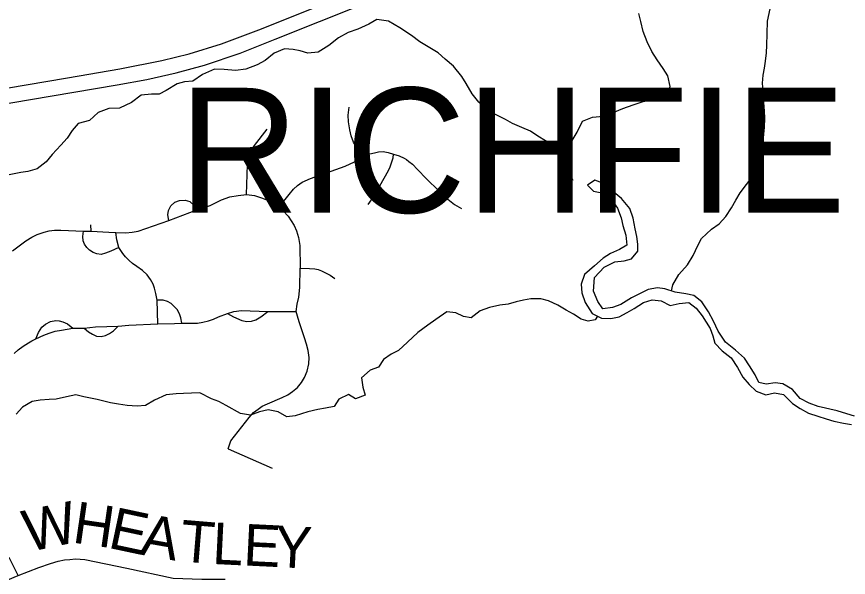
# Model space of a CAD drawing. Extents: x 0 to 34, y 0 to 22.
# Drawn here: x 6.774 to 7.911, y 17.175 to 17.94 of the extents above; entities that cross this region are included whole.
import ezdxf

# ---------------------------------------------------------------- set-up
doc = ezdxf.new("R2010")
doc.units = 0
for name, color, linetype in [('GM_X_County_Road', 7, 'Continuous'), ('GM_X_County_Road_Text', 7, 'Continuous'), ('GM_X_Interstate_Route', 7, 'Continuous'), ('GM_X_Minor_River', 7, 'Continuous'), ('GM_X_Township_Road', 7, 'Continuous'), ('GM_X_Township_Text', 7, 'Continuous')]:
    doc.layers.add(name, color=color, linetype=linetype)

msp = doc.modelspace()

# ---------------------------------------------------------------- linework, layer by layer
at = {"layer": 'GM_X_County_Road'}
msp.add_lwpolyline([(6.3969, 17.1561), (6.4792, 17.1605), (6.4835, 17.1608), (6.5551, 17.1657), (6.5991, 17.1683), (6.611, 17.1686), (6.6385, 17.1673), (6.6798, 17.1614), (6.7109, 17.1587), (6.7298, 17.1607), (6.7479, 17.1657), (6.7764, 17.1772), (6.8049, 17.1881), (6.8209, 17.1938), (6.8314, 17.197), (6.8397, 17.1986), (6.8472, 17.1994), (6.8548, 17.2001), (6.8677, 17.1991), (6.9249, 17.1872), (6.9884, 17.1736), (7.0275, 17.1723), (7.0591, 17.1724)], dxfattribs=at)
at = {"layer": 'GM_X_Interstate_Route'}
for points in [[(6.6481, 17.8024), (6.7935, 17.827), (6.9118, 17.8473), (6.9521, 17.8545), (6.9922, 17.8634), (7.0311, 17.8739), (7.0796, 17.8904), (7.1275, 17.9096), (7.3095, 17.9823)], [(6.7605, 17.8426), (6.8439, 17.8568), (6.9153, 17.869), (6.9726, 17.8806), (7.0103, 17.8893), (7.0541, 17.9032), (7.1051, 17.9225), (7.2044, 17.9618)]]:
    msp.add_lwpolyline(points, dxfattribs=at)
at = {"layer": 'GM_X_Minor_River'}
for points in [[(7.5348, 17.7166), (7.5279, 17.7283), (7.5247, 17.7442), (7.5257, 17.7587), (7.5321, 17.769), (7.5403, 17.7824), (7.5474, 17.7976), (7.561, 17.8031), (7.5757, 17.8044), (7.5886, 17.809), (7.6026, 17.8149), (7.6165, 17.8199), (7.6305, 17.8246), (7.6415, 17.8266), (7.6521, 17.8282), (7.6627, 17.8348), (7.6671, 17.8447), (7.664, 17.8595), (7.6578, 17.8693), (7.6494, 17.8814), (7.6421, 17.8927), (7.6359, 17.9059), (7.6305, 17.9199), (7.6269, 17.9336), (7.6242, 17.9446)], [(7.6689, 17.5659), (7.6709, 17.5743), (7.6788, 17.5881), (7.6908, 17.6015), (7.6987, 17.6141), (7.705, 17.6278), (7.7102, 17.6374), (7.7237, 17.65), (7.7339, 17.6574), (7.7433, 17.6673), (7.7508, 17.6792), (7.7568, 17.6899), (7.7627, 17.6998), (7.7714, 17.7113), (7.7837, 17.7269), (7.7893, 17.7376), (7.7923, 17.7491), (7.7937, 17.7601), (7.7947, 17.7749), (7.7961, 17.7894), (7.7967, 17.8019), (7.7959, 17.8114), (7.795, 17.8231), (7.7941, 17.8387), (7.7933, 17.8493), (7.794, 17.8604), (7.7962, 17.8699), (7.7972, 17.8794), (7.7986, 17.8908), (7.7993, 17.9014), (7.7995, 17.917), (7.8002, 17.9341), (7.8038, 17.9508)], [(7.5314, 17.768), (7.5222, 17.7697), (7.5101, 17.7665), (7.4968, 17.7709), (7.4865, 17.7773), (7.4762, 17.784), (7.4644, 17.7889), (7.4519, 17.7944), (7.4423, 17.7997), (7.4305, 17.8056), (7.4203, 17.8109), (7.4057, 17.8236), (7.3969, 17.8349), (7.3885, 17.8489), (7.3827, 17.8587), (7.3712, 17.8727), (7.3598, 17.8824), (7.3502, 17.8907), (7.3365, 17.8989), (7.3251, 17.906), (7.314, 17.9147), (7.298, 17.9252), (7.2824, 17.9341), (7.2664, 17.9362), (7.2555, 17.9301), (7.2404, 17.9231), (7.2272, 17.9188), (7.2143, 17.9114), (7.2008, 17.9007), (7.1865, 17.8918), (7.1721, 17.8905), (7.1618, 17.8935), (7.1523, 17.8953), (7.1405, 17.8963), (7.1262, 17.8905), (7.1138, 17.8805), (7.1028, 17.8743), (7.0877, 17.8685), (7.0733, 17.8668), (7.0578, 17.8682), (7.0449, 17.8688), (7.0283, 17.8611), (7.0151, 17.8522), (7.0037, 17.8513), (6.9939, 17.8486), (6.9788, 17.8393), (6.969, 17.8343), (6.9587, 17.8346), (6.9444, 17.8329), (6.9312, 17.8229), (6.9149, 17.8152), (6.9002, 17.815), (6.8858, 17.8092), (6.8738, 17.7985), (6.8586, 17.7945), (6.8504, 17.7849), (6.8433, 17.7742), (6.835, 17.7647), (6.823, 17.752), (6.8147, 17.7421), (6.8023, 17.7325), (6.7898, 17.7289), (6.78, 17.7277), (6.7618, 17.7241)], [(7.9189, 17.3948), (7.9086, 17.3981), (7.8953, 17.4022), (7.8695, 17.408), (7.8569, 17.4124), (7.8447, 17.4188), (7.8344, 17.4312), (7.8211, 17.439), (7.8104, 17.4405), (7.7983, 17.4385), (7.7885, 17.4406), (7.7831, 17.4512), (7.7757, 17.4637), (7.7685, 17.4742), (7.7562, 17.4848), (7.7429, 17.4957), (7.7329, 17.5107), (7.7263, 17.5244), (7.7194, 17.5372), (7.7106, 17.5508), (7.6995, 17.5594), (7.6885, 17.562), (7.6741, 17.5641), (7.66, 17.5689), (7.6498, 17.57), (7.6373, 17.5676), (7.6263, 17.5625), (7.6142, 17.5563), (7.5999, 17.5471), (7.5882, 17.5432), (7.5753, 17.5415), (7.5684, 17.5513), (7.5626, 17.5657), (7.564, 17.584), (7.5771, 17.5981), (7.5918, 17.6055), (7.6043, 17.6071), (7.6142, 17.6095), (7.6232, 17.6202), (7.6231, 17.6297), (7.6215, 17.64), (7.6195, 17.6506), (7.6167, 17.665), (7.6121, 17.6782), (7.6006, 17.6922), (7.588, 17.7027), (7.5777, 17.7121), (7.5643, 17.7169), (7.5542, 17.7104)], [(7.5542, 17.7104), (7.5626, 17.7021), (7.574, 17.6999), (7.5866, 17.6909), (7.5954, 17.6788), (7.6004, 17.6656), (7.6024, 17.655), (7.6067, 17.6421), (7.6079, 17.6284), (7.5981, 17.6226), (7.5857, 17.6168), (7.5755, 17.6107), (7.5638, 17.5999), (7.5503, 17.5884), (7.5455, 17.5751), (7.5467, 17.5633), (7.551, 17.55), (7.5606, 17.5349), (7.5732, 17.5286), (7.5861, 17.528), (7.5974, 17.5304), (7.6083, 17.5365), (7.6182, 17.5419), (7.6306, 17.55), (7.6427, 17.5539), (7.6548, 17.5525), (7.6674, 17.5458), (7.6795, 17.5486), (7.6928, 17.5499), (7.7027, 17.5424), (7.7111, 17.5318), (7.7219, 17.5144), (7.7254, 17.5046), (7.7281, 17.4944), (7.7384, 17.4842), (7.7506, 17.4745), (7.7591, 17.4612), (7.7664, 17.448), (7.7752, 17.4382), (7.7848, 17.4288), (7.7977, 17.424), (7.8098, 17.4268), (7.822, 17.4246), (7.8342, 17.4122), (7.8449, 17.4051), (7.8563, 17.3991), (7.8688, 17.3947), (7.8802, 17.391), (7.8909, 17.3881), (7.9038, 17.3851), (7.9148, 17.3837)], [(7.5677, 17.5313), (7.5648, 17.5262), (7.555, 17.5246), (7.5455, 17.5272), (7.5352, 17.5343), (7.5249, 17.5395), (7.5139, 17.5463), (7.5009, 17.5522), (7.4903, 17.5552), (7.4767, 17.555), (7.4668, 17.5534), (7.4566, 17.551), (7.446, 17.5479), (7.4343, 17.5463), (7.4203, 17.5431), (7.4078, 17.5388), (7.3954, 17.5292), (7.3847, 17.531), (7.3745, 17.5358), (7.3623, 17.5372), (7.3469, 17.5268), (7.336, 17.5191), (7.3224, 17.5091), (7.3085, 17.4957), (7.2961, 17.4846), (7.2859, 17.4795), (7.2757, 17.4722), (7.2686, 17.4619), (7.2573, 17.4576), (7.2456, 17.4473), (7.2472, 17.4344), (7.2504, 17.4234), (7.2375, 17.4183), (7.228, 17.4243), (7.2144, 17.4181), (7.2084, 17.4082), (7.1963, 17.4058), (7.1857, 17.4038), (7.1721, 17.4006), (7.1551, 17.3955), (7.1437, 17.3939), (7.1319, 17.401), (7.1182, 17.4035), (7.1061, 17.4007), (7.0937, 17.3964), (7.0804, 17.3986), (7.0609, 17.4094), (7.0507, 17.415), (7.0408, 17.4187), (7.0248, 17.4266), (7.0134, 17.4261), (7.0024, 17.426), (6.9922, 17.4255), (6.9786, 17.4238), (6.9627, 17.4165), (6.9503, 17.4095), (6.9389, 17.4087), (6.9256, 17.4093), (6.9135, 17.4114), (6.9028, 17.4132), (6.8846, 17.4176), (6.8664, 17.4213), (6.8554, 17.4238), (6.8425, 17.4214), (6.8285, 17.4179), (6.8187, 17.4174), (6.8065, 17.4169), (6.7959, 17.4149), (6.7824, 17.4072), (6.7737, 17.3976)]]:
    msp.add_lwpolyline(points, dxfattribs=at)
at = {"layer": 'GM_X_Township_Road'}
for p, q in [((6.8761, 17.6472), (6.8756, 17.6559)), ((7.0633, 17.3501), (7.1234, 17.3238))]:
    msp.add_line(p, q, dxfattribs=at)
for points in [[(7.2469, 17.7481), (7.2347, 17.769), (7.2314, 17.7776), (7.2294, 17.7858), (7.2279, 17.7968), (7.2275, 17.8056), (7.2288, 17.8165)], [(7.0885, 17.6977), (7.0896, 17.7386), (7.0909, 17.7453), (7.0926, 17.7507), (7.0949, 17.7571), (7.0993, 17.7642), (7.1165, 17.7866)], [(7.1333, 17.6809), (7.1413, 17.6907), (7.1467, 17.6974), (7.1525, 17.7049), (7.1579, 17.7098), (7.1647, 17.7143), (7.1758, 17.7195), (7.2104, 17.7314), (7.2232, 17.7361), (7.236, 17.7423), (7.2469, 17.7481), (7.257, 17.7529), (7.2633, 17.7545), (7.2686, 17.7555), (7.2751, 17.7561), (7.2818, 17.7547), (7.2892, 17.7527), (7.2971, 17.7502), (7.3037, 17.7473), (7.3071, 17.7454), (7.3104, 17.7427), (7.315, 17.7391), (7.3222, 17.7316), (7.3343, 17.719), (7.351, 17.7023), (7.3588, 17.6947), (7.3658, 17.6891), (7.3726, 17.6839), (7.3822, 17.6785)], [(7.2546, 17.6837), (7.2622, 17.6947), (7.2765, 17.7198), (7.2826, 17.7303), (7.2845, 17.7351), (7.287, 17.7421), (7.2889, 17.7475), (7.2892, 17.7527)], [(6.7688, 17.6206), (6.7872, 17.6341), (6.7952, 17.6392), (6.8027, 17.6428), (6.812, 17.646), (6.8187, 17.6478), (6.8264, 17.649), (6.8349, 17.649), (6.866, 17.6475), (6.8761, 17.6472), (6.9005, 17.646), (6.9101, 17.6454), (6.9237, 17.6452), (6.9323, 17.6459), (6.9404, 17.6475), (6.9824, 17.6618), (7.0206, 17.6765), (7.0387, 17.6824), (7.0542, 17.6901), (7.0656, 17.6943), (7.0772, 17.6962), (7.0885, 17.6977), (7.0992, 17.696), (7.109, 17.6931), (7.1171, 17.6896), (7.1264, 17.6852), (7.1333, 17.6809), (7.1385, 17.6754), (7.1453, 17.6678), (7.1496, 17.6615), (7.1534, 17.6552), (7.1566, 17.6479), (7.1595, 17.6389), (7.1612, 17.628), (7.1618, 17.5967)], [(6.9824, 17.6618), (6.9812, 17.6698), (6.9821, 17.6757), (6.985, 17.6819), (6.9907, 17.6868), (6.9968, 17.6892), (7.0046, 17.6897), (7.011, 17.6878), (7.0165, 17.683), (7.0206, 17.6765)], [(6.914, 17.6253), (6.9033, 17.6203), (6.896, 17.6174), (6.8897, 17.6156), (6.8838, 17.6166), (6.8789, 17.6183), (6.8741, 17.6217), (6.8703, 17.6252), (6.8672, 17.6295), (6.8655, 17.6344), (6.865, 17.64), (6.866, 17.6475)], [(6.9675, 17.521), (6.9663, 17.5531), (6.9646, 17.5625), (6.9628, 17.5695), (6.9609, 17.5752), (6.9574, 17.5816), (6.9528, 17.5878), (6.9466, 17.5938), (6.9388, 17.5994), (6.9329, 17.6034), (6.928, 17.6072), (6.9232, 17.6125), (6.9197, 17.6171), (6.914, 17.6253), (6.9115, 17.6358), (6.9101, 17.6454)], [(7.0633, 17.3501), (7.0672, 17.3612), (7.0922, 17.3931), (7.0979, 17.3999), (7.1043, 17.4046), (7.11, 17.4085), (7.1173, 17.4117), (7.1372, 17.4203), (7.1447, 17.4241), (7.1513, 17.4284), (7.158, 17.434), (7.1636, 17.4408), (7.1677, 17.4475), (7.1712, 17.4561), (7.1736, 17.4661), (7.1742, 17.475), (7.1728, 17.4844), (7.1704, 17.493), (7.1677, 17.5016), (7.1602, 17.5237), (7.1582, 17.5315), (7.1561, 17.5378), (7.1576, 17.5477), (7.1599, 17.5575), (7.1612, 17.5706), (7.1618, 17.5967)], [(7.1618, 17.5967), (7.1747, 17.5966), (7.1817, 17.5959), (7.1865, 17.595), (7.1909, 17.5932), (7.1965, 17.5905), (7.2027, 17.5872), (7.2089, 17.583)], [(7.0003, 17.5218), (6.9988, 17.5289), (6.997, 17.5347), (6.9939, 17.5406), (6.9894, 17.5452), (6.9857, 17.5487), (6.9804, 17.5513), (6.9745, 17.5531), (6.9663, 17.5531)], [(6.7709, 17.4802), (6.7767, 17.4852), (6.7836, 17.4906), (6.7907, 17.4951), (6.7953, 17.4978), (6.8007, 17.5004), (6.8117, 17.5056), (6.819, 17.5083), (6.8272, 17.5108), (6.8356, 17.5124), (6.8437, 17.5138), (6.8514, 17.5151), (6.8669, 17.5149), (6.882, 17.5166), (6.9133, 17.5176), (6.9275, 17.5189), (6.9675, 17.521), (6.99, 17.5212), (7.0003, 17.5218), (7.0217, 17.5219), (7.0289, 17.5231), (7.0364, 17.5248), (7.0433, 17.5275), (7.0504, 17.5306), (7.0625, 17.5349), (7.0713, 17.5378), (7.0815, 17.5393), (7.1175, 17.5379), (7.1561, 17.5378)], [(7.0625, 17.5349), (7.0708, 17.5306), (7.0822, 17.5255), (7.0889, 17.5239), (7.0954, 17.5245), (7.1012, 17.5265), (7.1079, 17.5306), (7.1175, 17.5379)], [(6.8007, 17.5004), (6.8042, 17.509), (6.8091, 17.5164), (6.8137, 17.5204), (6.8209, 17.5241), (6.8279, 17.5253), (6.8326, 17.5251), (6.8375, 17.5238), (6.8441, 17.5208), (6.8514, 17.5151)], [(6.8669, 17.5149), (6.8728, 17.5102), (6.8781, 17.5068), (6.8835, 17.5043), (6.89, 17.5038), (6.8959, 17.5052), (6.9014, 17.5078), (6.9068, 17.5115), (6.9133, 17.5176)], [(6.7764, 17.1772), (6.7643, 17.2021)]]:
    msp.add_lwpolyline(points, dxfattribs=at)

# ---------------------------------------------------------------- texts
at = {"layer": 'GM_X_County_Road_Text'}
for s, rotation, p in [('W', 11.8227, (6.79, 17.2091)), ('H', 351.7792, (6.8492, 17.2225)), ('E', 347.9941, (6.8977, 17.2155)), ('A', 350.0253, (6.9414, 17.2062)), ('T', 355.2962, (6.9963, 17.1968)), ('L', 357.1945, (7.0408, 17.1932)), ('E', 357.2048, (7.0832, 17.1912)), ('Y', 357.0115, (7.1256, 17.1891))]:
    msp.add_text(s, height=0.0568, rotation=rotation, dxfattribs=at).set_placement(p)
at = {"layer": 'GM_X_Township_Text'}
msp.add_text('RICHFIELD', height=0.17045, rotation=0, dxfattribs=at).set_placement((6.9956, 17.6727))

doc.saveas('drawing.dxf')
